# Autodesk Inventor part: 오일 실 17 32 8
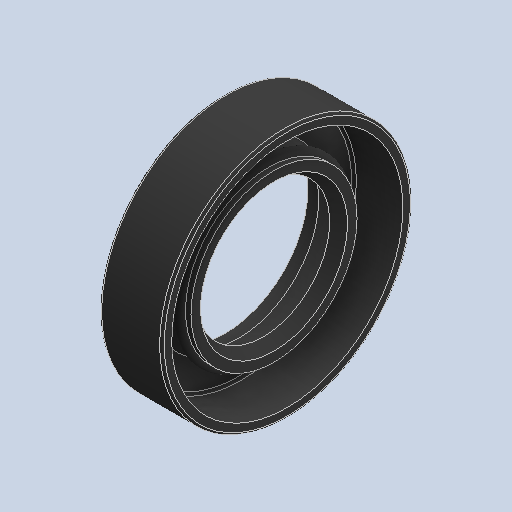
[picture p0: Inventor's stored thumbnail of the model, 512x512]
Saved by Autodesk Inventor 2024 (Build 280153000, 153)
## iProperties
Created: 2026-01
Part Number: 오일 실 17 32 8
Material: 고무
Description: 오일-실
Document SubType Name: Modeling
Designer: 2-10
Density: 0.93 g/cm^3
Appearance: 기본값
Sending System: Autodesk Inventor 2026
Preprocessor: ST-DEVELOPER v20.1
Author: jhkim
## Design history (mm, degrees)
node "오일 실 17 32 81"
node "솔리드1"
body "Solid1"
